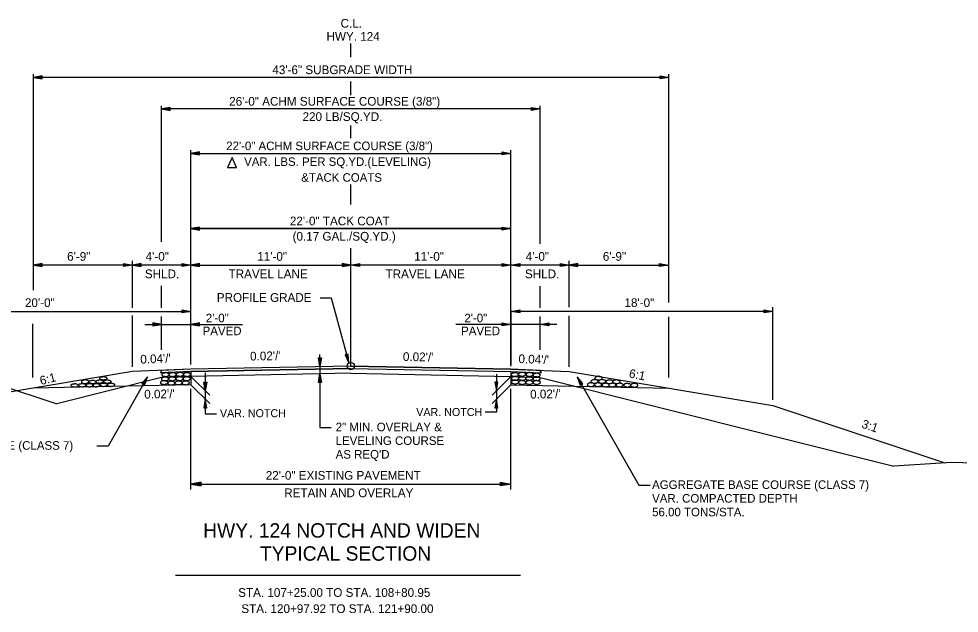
# Model space of a CAD drawing. Extents: x 1824008 to 1828864, y 689441 to 689870.
# Drawn here: x 1828762.4 to 1828827, y 689829.6 to 689870.4 of the extents above; entities that cross this region are included whole.
import ezdxf

# ---------------------------------------------------------------- set-up
doc = ezdxf.new("R2010")
doc.units = 0
for name, color, linetype in [('1', 7, 'Continuous'), ('10', 7, 'Continuous'), ('19', 7, 'Continuous'), ('Level 1', 7, 'Continuous'), ('R_Draft', 7, 'Continuous'), ('R_Horz Alg', 7, 'Continuous')]:
    doc.layers.add(name, color=color, linetype=linetype)

# ---------------------------------------------------------------- blocks, each defined once
blk = doc.blocks.new('ROCKS')
at = {"layer": '1'}
blk.add_spline([(0.013, 0.06), (0.053, 0.053), (0.107, 0.033), (0.133, 0.013), (0.133, -0.007), (0.12, -0.033), (0.107, -0.04), (0.073, -0.053), (0.033, -0.067), (0.013, -0.067), (-0.02, -0.06), (-0.06, -0.053), (-0.087, -0.047), (-0.113, -0.02), (-0.113, -0.007), (-0.107, 0.02), (-0.087, 0.033), (-0.067, 0.047), (-0.033, 0.053), (-0.02, 0.06), (0.013, 0.06)], degree=3, dxfattribs=at)
blk = doc.blocks.new('4TO1 ABC')
at = {"layer": '1', "xscale": 0.1312491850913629, "yscale": 0.1312491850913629, "rotation": 180}
for p in [(0.00175, -0.00875), (-0.03325, -0.0385), (-0.016625, -0.023625), (0, -0.0385), (0.018375, -0.023625), (0.034125, -0.04025), (0.051625, -0.025375), (0.06475, -0.04025), (0.098, -0.04025), (0.133, -0.041125)]:
    blk.add_blockref('ROCKS', p, dxfattribs=at)

msp = doc.modelspace()

# ---------------------------------------------------------------- linework, layer by layer
at = {"layer": '1'}
for p, q in [((1828764.008, 689866.485), (1828763.408, 689866.38)), ((1828763.408, 689866.38), (1828764.008, 689866.275)), ((1828764.008, 689866.43), (1828763.568, 689866.395)), ((1828763.568, 689866.365), (1828764.008, 689866.325)), ((1828764.008, 689866.275), (1828764.008, 689866.485)), ((1828806.466, 689866.275), (1828806.466, 689866.485)), ((1828806.466, 689866.485), (1828807.066, 689866.38)), ((1828806.466, 689866.43), (1828806.906, 689866.395)), ((1828807.066, 689866.38), (1828806.466, 689866.275)), ((1828806.906, 689866.365), (1828806.466, 689866.325)), ((1828772.815, 689864.317), (1828772.215, 689864.212)), ((1828772.215, 689864.212), (1828772.815, 689864.107)), ((1828772.815, 689864.262), (1828772.375, 689864.227)), ((1828772.375, 689864.197), (1828772.815, 689864.157)), ((1828772.815, 689864.107), (1828772.815, 689864.317)), ((1828797.624, 689864.107), (1828797.624, 689864.317)), ((1828797.624, 689864.317), (1828798.224, 689864.212)), ((1828797.624, 689864.262), (1828798.064, 689864.227)), ((1828798.224, 689864.212), (1828797.624, 689864.107)), ((1828798.064, 689864.197), (1828797.624, 689864.157)), ((1828774.82, 689861.268), (1828774.22, 689861.163)), ((1828774.22, 689861.163), (1828774.82, 689861.058)), ((1828774.82, 689861.213), (1828774.38, 689861.178)), ((1828774.82, 689861.058), (1828774.82, 689861.268)), ((1828795.62, 689861.058), (1828795.62, 689861.268)), ((1828795.62, 689861.268), (1828796.22, 689861.163)), ((1828795.62, 689861.213), (1828796.06, 689861.178)), ((1828796.22, 689861.163), (1828795.62, 689861.058)), ((1828774.38, 689861.148), (1828774.82, 689861.108)), ((1828777.071, 689860.871), (1828776.754, 689860.203)), ((1828777.363, 689860.203), (1828777.071, 689860.871)), ((1828796.06, 689861.148), (1828795.62, 689861.108)), ((1828776.754, 689860.203), (1828777.363, 689860.203)), ((1828774.82, 689856.097), (1828774.22, 689855.992)), ((1828774.22, 689855.992), (1828774.82, 689855.887)), ((1828774.82, 689856.042), (1828774.38, 689856.007)), ((1828774.82, 689855.887), (1828774.82, 689856.097)), ((1828795.62, 689855.887), (1828795.62, 689856.097)), ((1828795.62, 689856.097), (1828796.22, 689855.992)), ((1828795.62, 689856.042), (1828796.06, 689856.007)), ((1828796.22, 689855.992), (1828795.62, 689855.887)), ((1828774.38, 689855.977), (1828774.82, 689855.937)), ((1828796.06, 689855.977), (1828795.62, 689855.937)), ((1828764.008, 689853.591), (1828763.408, 689853.486)), ((1828763.408, 689853.486), (1828764.008, 689853.381)), ((1828764.008, 689853.536), (1828763.568, 689853.501)), ((1828763.568, 689853.471), (1828764.008, 689853.431)), ((1828764.008, 689853.381), (1828764.008, 689853.591)), ((1828769.62, 689853.381), (1828769.62, 689853.591)), ((1828769.62, 689853.591), (1828770.22, 689853.486)), ((1828769.62, 689853.536), (1828770.06, 689853.501)), ((1828770.22, 689853.486), (1828769.62, 689853.381)), ((1828770.06, 689853.471), (1828769.62, 689853.431)), ((1828770.22, 689850.55), (1828770.22, 689853.786)), ((1828770.82, 689853.591), (1828770.22, 689853.486)), ((1828770.22, 689853.486), (1828770.82, 689853.381)), ((1828770.82, 689853.536), (1828770.38, 689853.501)), ((1828770.38, 689853.471), (1828770.82, 689853.431)), ((1828770.82, 689853.381), (1828770.82, 689853.591)), ((1828773.62, 689853.381), (1828773.62, 689853.591)), ((1828773.62, 689853.591), (1828774.22, 689853.486)), ((1828773.62, 689853.536), (1828774.06, 689853.501)), ((1828774.22, 689853.486), (1828773.62, 689853.381)), ((1828774.06, 689853.471), (1828773.62, 689853.431)), ((1828774.22, 689846.656), (1828774.22, 689853.786)), ((1828774.82, 689853.591), (1828774.22, 689853.486)), ((1828774.22, 689853.486), (1828785.22, 689853.486)), ((1828774.22, 689853.486), (1828774.82, 689853.381)), ((1828774.82, 689853.536), (1828774.38, 689853.501)), ((1828774.38, 689853.471), (1828774.82, 689853.431)), ((1828774.82, 689853.381), (1828774.82, 689853.591)), ((1828775.22, 689853.486), (1828785.22, 689853.486)), ((1828775.22, 689853.486), (1828785.22, 689853.486)), ((1828784.62, 689853.591), (1828784.62, 689853.381)), ((1828785.22, 689853.486), (1828784.62, 689853.591)), ((1828784.62, 689853.591), (1828784.62, 689853.381)), ((1828785.22, 689853.486), (1828784.62, 689853.591)), ((1828785.06, 689853.501), (1828784.62, 689853.536)), ((1828785.06, 689853.501), (1828784.62, 689853.536)), ((1828784.62, 689853.381), (1828785.22, 689853.486)), ((1828784.62, 689853.381), (1828785.22, 689853.486)), ((1828784.62, 689853.431), (1828785.06, 689853.471)), ((1828784.62, 689853.431), (1828785.06, 689853.471)), ((1828785.22, 689853.486), (1828785.82, 689853.591)), ((1828785.22, 689853.486), (1828785.82, 689853.591)), ((1828795.22, 689853.486), (1828785.22, 689853.486)), ((1828785.82, 689853.381), (1828785.22, 689853.486)), ((1828796.22, 689853.486), (1828785.22, 689853.486)), ((1828785.82, 689853.381), (1828785.22, 689853.486)), ((1828785.38, 689853.501), (1828785.82, 689853.536)), ((1828785.38, 689853.501), (1828785.82, 689853.536)), ((1828785.82, 689853.431), (1828785.38, 689853.471)), ((1828785.82, 689853.431), (1828785.38, 689853.471)), ((1828785.82, 689853.591), (1828785.82, 689853.381)), ((1828785.82, 689853.591), (1828785.82, 689853.381)), ((1828795.62, 689853.381), (1828795.62, 689853.591)), ((1828795.62, 689853.591), (1828796.22, 689853.486)), ((1828795.62, 689853.536), (1828796.06, 689853.501)), ((1828796.22, 689853.486), (1828795.62, 689853.381)), ((1828796.06, 689853.471), (1828795.62, 689853.431)), ((1828796.22, 689846.656), (1828796.22, 689853.786)), ((1828796.22, 689853.486), (1828796.82, 689853.591)), ((1828796.82, 689853.381), (1828796.22, 689853.486)), ((1828796.38, 689853.501), (1828796.82, 689853.536)), ((1828796.82, 689853.431), (1828796.38, 689853.471)), ((1828796.82, 689853.591), (1828796.82, 689853.381)), ((1828799.62, 689853.381), (1828799.62, 689853.591)), ((1828799.62, 689853.591), (1828800.22, 689853.486)), ((1828799.62, 689853.536), (1828800.06, 689853.501)), ((1828800.22, 689853.486), (1828799.62, 689853.381)), ((1828800.06, 689853.471), (1828799.62, 689853.431)), ((1828800.82, 689853.591), (1828800.22, 689853.486)), ((1828800.22, 689853.486), (1828800.82, 689853.381)), ((1828800.82, 689853.536), (1828800.38, 689853.501)), ((1828800.38, 689853.471), (1828800.82, 689853.431)), ((1828800.82, 689853.381), (1828800.82, 689853.591)), ((1828806.431, 689853.381), (1828806.431, 689853.591)), ((1828806.431, 689853.591), (1828807.031, 689853.486)), ((1828806.431, 689853.536), (1828806.871, 689853.501)), ((1828807.031, 689853.486), (1828806.431, 689853.381)), ((1828806.871, 689853.471), (1828806.431, 689853.431)), ((1828772.22, 689850.55), (1828772.22, 689852.059)), ((1828798.22, 689850.55), (1828798.22, 689852.047)), ((1828754.22, 689850.307), (1828774.22, 689850.307)), ((1828773.62, 689850.202), (1828773.62, 689850.412)), ((1828773.62, 689850.412), (1828774.22, 689850.307)), ((1828773.62, 689850.357), (1828774.06, 689850.322)), ((1828774.22, 689850.307), (1828773.62, 689850.202)), ((1828774.06, 689850.292), (1828773.62, 689850.252)), ((1828796.22, 689850.307), (1828796.82, 689850.412)), ((1828814.22, 689850.307), (1828796.22, 689850.307)), ((1828796.82, 689850.202), (1828796.22, 689850.307)), ((1828796.38, 689850.322), (1828796.82, 689850.357)), ((1828796.82, 689850.252), (1828796.38, 689850.292)), ((1828796.82, 689850.412), (1828796.82, 689850.202)), ((1828813.62, 689850.202), (1828813.62, 689850.412)), ((1828813.62, 689850.412), (1828814.22, 689850.307)), ((1828813.62, 689850.357), (1828814.06, 689850.322)), ((1828814.22, 689850.307), (1828813.62, 689850.202)), ((1828814.06, 689850.292), (1828813.62, 689850.252)), ((1828770.22, 689846.496), (1828770.22, 689850.032)), ((1828772.22, 689847.657), (1828772.22, 689849.961)), ((1828798.22, 689847.657), (1828798.22, 689849.961)), ((1828751.824, 689848.348), (1828765.008, 689843.953)), ((1828774.22, 689846.336), (1828770.22, 689846.176)), ((1828774.22, 689846.336), (1828770.22, 689846.176)), ((1828785.22, 689846.556), (1828774.22, 689846.336)), ((1828785.22, 689846.556), (1828774.22, 689846.336)), ((1828785.223, 689846.389), (1828774.223, 689846.169)), ((1828785.216, 689846.389), (1828796.22, 689846.169)), ((1828785.22, 689846.556), (1828796.22, 689846.336)), ((1828796.22, 689846.336), (1828800.22, 689846.176)), ((1828772.22, 689845.756), (1828765.008, 689843.953)), ((1828774.226, 689846.169), (1828772.135, 689846.086)), ((1828774.22, 689845.836), (1828772.22, 689845.756)), ((1828774.22, 689846.169), (1828774.22, 689845.253)), ((1828785.22, 689846.056), (1828774.22, 689845.836)), ((1828774.22, 689845.836), (1828775.52, 689844.564)), ((1828785.22, 689846.056), (1828796.22, 689845.836)), ((1828796.22, 689845.836), (1828794.92, 689844.564)), ((1828796.22, 689846.169), (1828796.22, 689845.253)), ((1828796.22, 689846.169), (1828798.305, 689846.086)), ((1828796.22, 689845.836), (1828798.22, 689845.756)), ((1828798.22, 689845.756), (1828822.529, 689839.679)), ((1828774.22, 689845.253), (1828763.379, 689845.036)), ((1828774.22, 689845.253), (1828775.52, 689843.98)), ((1828775.115, 689845.457), (1828775.325, 689845.457)), ((1828775.22, 689844.857), (1828775.115, 689845.457)), ((1828775.205, 689845.017), (1828775.165, 689845.457)), ((1828775.325, 689845.457), (1828775.22, 689844.857)), ((1828775.27, 689845.457), (1828775.235, 689845.017)), ((1828796.22, 689845.253), (1828794.92, 689843.98)), ((1828795.325, 689845.457), (1828795.115, 689845.457)), ((1828795.115, 689845.457), (1828795.22, 689844.857)), ((1828795.17, 689845.457), (1828795.205, 689845.017)), ((1828795.22, 689844.857), (1828795.325, 689845.457)), ((1828795.235, 689845.017), (1828795.275, 689845.457)), ((1828796.22, 689845.253), (1828807.061, 689845.036)), ((1828774.22, 689838.07), (1828774.22, 689844.993)), ((1828796.22, 689838.07), (1828796.22, 689844.993)), ((1828775.22, 689844.274), (1828775.115, 689843.674)), ((1828775.205, 689844.114), (1828775.165, 689843.674)), ((1828775.325, 689843.674), (1828775.22, 689844.274)), ((1828775.27, 689843.674), (1828775.235, 689844.114)), ((1828795.22, 689844.274), (1828795.115, 689843.674)), ((1828795.205, 689844.114), (1828795.165, 689843.674)), ((1828795.325, 689843.674), (1828795.22, 689844.274)), ((1828795.27, 689843.674), (1828795.235, 689844.114)), ((1828814.22, 689843.843), (1828826.024, 689839.908)), ((1828775.115, 689843.674), (1828775.325, 689843.674)), ((1828795.115, 689843.674), (1828795.325, 689843.674)), ((1828774.935, 689838.57), (1828774.22, 689838.445)), ((1828774.935, 689838.319), (1828774.935, 689838.57)), ((1828795.504, 689838.319), (1828795.504, 689838.57)), ((1828795.504, 689838.57), (1828796.22, 689838.445)), ((1828774.22, 689838.445), (1828796.22, 689838.445)), ((1828774.22, 689838.445), (1828774.935, 689838.319)), ((1828774.935, 689838.504), (1828774.41, 689838.462)), ((1828774.41, 689838.427), (1828774.935, 689838.379)), ((1828795.504, 689838.504), (1828796.029, 689838.462)), ((1828796.22, 689838.445), (1828795.504, 689838.319)), ((1828796.029, 689838.427), (1828795.504, 689838.379)), ((1828773.166, 689832.197), (1828796.878, 689832.197))]:
    msp.add_line(p, q, dxfattribs=at)
for points in [[(1828775.22, 689846.079), (1828775.22, 689843.261), (1828775.996, 689843.261)], [(1828795.22, 689846.007), (1828795.22, 689843.396), (1828794.443, 689843.396)], [(1828852.627, 689840.421), (1828844.044, 689840.132), (1828832.759, 689839.746), (1828826.49, 689839.939), (1828822.529, 689839.679)]]:
    msp.add_lwpolyline(points, dxfattribs=at)
msp.add_circle((1828785.215, 689846.554), 0.25, dxfattribs=at)
at = {"layer": '19'}
for p, q in [((1828763.408, 689851.76), (1828763.408, 689866.605)), ((1828807.066, 689866.38), (1828763.408, 689866.38)), ((1828807.066, 689850.917), (1828807.066, 689866.605)), ((1828772.215, 689855.084), (1828772.215, 689864.437)), ((1828798.224, 689854.955), (1828798.224, 689864.437)), ((1828798.224, 689864.212), (1828772.215, 689864.212)), ((1828774.22, 689861.163), (1828796.22, 689861.163)), ((1828774.22, 689854.515), (1828774.22, 689856.217)), ((1828774.22, 689855.992), (1828796.22, 689855.992)), ((1828796.22, 689855.992), (1828774.22, 689855.992)), ((1828796.22, 689856.195), (1828796.22, 689856.217)), ((1828771.06, 689849.418), (1828777.786, 689849.418)), ((1828771.615, 689849.523), (1828771.615, 689849.313)), ((1828772.215, 689849.418), (1828771.615, 689849.523)), ((1828772.055, 689849.433), (1828771.615, 689849.468)), ((1828771.615, 689849.313), (1828772.215, 689849.418)), ((1828771.615, 689849.363), (1828772.055, 689849.403)), ((1828774.815, 689849.523), (1828774.215, 689849.418)), ((1828774.215, 689849.418), (1828774.815, 689849.313)), ((1828774.815, 689849.468), (1828774.375, 689849.433)), ((1828774.375, 689849.403), (1828774.815, 689849.363)), ((1828774.815, 689849.313), (1828774.815, 689849.523)), ((1828799.38, 689849.418), (1828792.437, 689849.418)), ((1828795.624, 689849.313), (1828795.624, 689849.523)), ((1828795.624, 689849.523), (1828796.224, 689849.418)), ((1828795.624, 689849.468), (1828796.064, 689849.433)), ((1828796.224, 689849.418), (1828795.624, 689849.313)), ((1828796.064, 689849.403), (1828795.624, 689849.363)), ((1828798.224, 689849.418), (1828798.824, 689849.523)), ((1828798.824, 689849.313), (1828798.224, 689849.418)), ((1828798.384, 689849.433), (1828798.824, 689849.468)), ((1828798.824, 689849.363), (1828798.384, 689849.403)), ((1828798.824, 689849.523), (1828798.824, 689849.313)), ((1828782.995, 689847.114), (1828783.205, 689847.114)), ((1828783.1, 689846.514), (1828782.995, 689847.114)), ((1828783.085, 689846.674), (1828783.045, 689847.114)), ((1828783.1, 689846.514), (1828783.1, 689847.346)), ((1828783.205, 689847.114), (1828783.1, 689846.514)), ((1828783.15, 689847.114), (1828783.115, 689846.674)), ((1828774.22, 689846.336), (1828772.22, 689846.256)), ((1828785.22, 689846.556), (1828774.22, 689846.336)), ((1828774.223, 689846.169), (1828785.223, 689846.389)), ((1828783.1, 689846.551), (1828783.1, 689842.332)), ((1828796.22, 689846.336), (1828785.22, 689846.556)), ((1828785.223, 689846.389), (1828796.22, 689846.169)), ((1828798.22, 689846.256), (1828796.22, 689846.336)), ((1828770.22, 689846.176), (1828754.22, 689843.509)), ((1828771.251, 689845.815), (1828768.542, 689841.062)), ((1828771.251, 689845.815), (1828770.863, 689845.346)), ((1828771.159, 689845.684), (1828770.907, 689845.321)), ((1828770.998, 689845.269), (1828771.185, 689845.669)), ((1828771.046, 689845.242), (1828771.251, 689845.815)), ((1828772.22, 689846.256), (1828772.135, 689846.086)), ((1828772.22, 689846.256), (1828772.135, 689846.086)), ((1828772.135, 689846.086), (1828774.223, 689846.169)), ((1828782.995, 689845.414), (1828783.1, 689846.014)), ((1828783.05, 689845.414), (1828783.085, 689845.854)), ((1828783.1, 689846.014), (1828783.205, 689845.414)), ((1828783.115, 689845.854), (1828783.155, 689845.414)), ((1828796.22, 689846.169), (1828798.305, 689846.086)), ((1828798.22, 689846.256), (1828798.304, 689846.086)), ((1828798.22, 689846.256), (1828798.304, 689846.086)), ((1828798.305, 689846.086), (1828798.22, 689846.256)), ((1828800.22, 689846.176), (1828814.22, 689843.843)), ((1828800.775, 689845.815), (1828805.019, 689838.371)), ((1828801.163, 689845.346), (1828800.775, 689845.815)), ((1828800.775, 689845.815), (1828800.981, 689845.242)), ((1828800.841, 689845.669), (1828801.024, 689845.267)), ((1828801.115, 689845.319), (1828800.867, 689845.684)), ((1828770.863, 689845.346), (1828771.046, 689845.242)), ((1828783.205, 689845.414), (1828782.995, 689845.414)), ((1828800.981, 689845.242), (1828801.163, 689845.346)), ((1828783.1, 689842.332), (1828783.866, 689842.332)), ((1828768.542, 689841.062), (1828767.775, 689841.062)), ((1828805.019, 689838.371), (1828805.785, 689838.371))]:
    msp.add_line(p, q, dxfattribs=at)
for points in [[(1828774.22, 689853.486), (1828774.22, 689861.384)], [(1828796.22, 689853.486), (1828796.22, 689857.675), (1828796.22, 689861.384)], [(1828774.22, 689853.786), (1828774.22, 689853.786), (1828774.22, 689856.385)]]:
    msp.add_lwpolyline(points, dxfattribs=at)
at = {"layer": 'R_Draft'}
for p, q in [((1828785.22, 689867.761), (1828785.22, 689868.704)), ((1828785.22, 689865.162), (1828785.22, 689866.104)), ((1828785.22, 689862.201), (1828785.22, 689863.08)), ((1828785.22, 689857.657), (1828785.22, 689859.014)), ((1828785.22, 689846.556), (1828785.22, 689854.643)), ((1828770.22, 689853.486), (1828763.408, 689853.486)), ((1828774.22, 689853.486), (1828770.22, 689853.486)), ((1828775.22, 689853.486), (1828785.22, 689853.486)), ((1828784.62, 689853.591), (1828784.62, 689853.381)), ((1828785.22, 689853.486), (1828784.62, 689853.591)), ((1828785.06, 689853.501), (1828784.62, 689853.536)), ((1828784.62, 689853.381), (1828785.22, 689853.486)), ((1828784.62, 689853.431), (1828785.06, 689853.471)), ((1828785.22, 689853.486), (1828785.82, 689853.591)), ((1828795.22, 689853.486), (1828785.22, 689853.486)), ((1828785.82, 689853.381), (1828785.22, 689853.486)), ((1828785.38, 689853.501), (1828785.82, 689853.536)), ((1828785.82, 689853.431), (1828785.38, 689853.471)), ((1828785.82, 689853.591), (1828785.82, 689853.381)), ((1828800.22, 689853.486), (1828796.22, 689853.486)), ((1828800.22, 689850.607), (1828800.22, 689853.786)), ((1828800.22, 689853.486), (1828807.031, 689853.486)), ((1828800.22, 689846.496), (1828800.22, 689850.007)), ((1828785.03, 689847.376), (1828784.829, 689847.319)), ((1828784.829, 689847.319), (1828785.088, 689846.769)), ((1828784.874, 689847.329), (1828785.031, 689846.92)), ((1828785.056, 689846.925), (1828784.98, 689847.357)), ((1828785.088, 689846.769), (1828785.03, 689847.376))]:
    msp.add_line(p, q, dxfattribs=at)
msp.add_lwpolyline([(1828783.12, 689851.249), (1828783.857, 689851.248), (1828785.088, 689846.769)], dxfattribs=at)
at = {"layer": 'R_Horz Alg'}
for p, q in [((1828796.22, 689846.556), (1828796.22, 689850.912)), ((1828796.22, 689850.307), (1828796.22, 689846.62)), ((1828814.22, 689844.23), (1828814.22, 689850.607)), ((1828807.061, 689845.756), (1828807.061, 689849.941)), ((1828763.379, 689845.756), (1828763.379, 689849.455))]:
    msp.add_line(p, q, dxfattribs=at)

# ---------------------------------------------------------------- block references
at = {"layer": '19', "xscale": 14.999970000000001, "yscale": -14.999970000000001, "rotation": 180}
msp.add_blockref('4TO1 ABC', (1828768.225, 689845.834), dxfattribs=at)
at = {"layer": '19', "xscale": 14.999970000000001, "yscale": 14.999970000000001}
msp.add_blockref('4TO1 ABC', (1828802.231, 689845.847), dxfattribs=at)
at = {"layer": 'Level 1', "xscale": 2.0116542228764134}
for p, yscale, rotation in [((1828772.431, 689845.673), 2.0116542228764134, 0.3302009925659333), ((1828772.46, 689845.97), 2.0116542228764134, 0.3302009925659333), ((1828772.927, 689845.683), 2.0116542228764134, 0.3302009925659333), ((1828772.956, 689845.973), 2.0116542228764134, 0.3302009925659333), ((1828773.427, 689845.693), 2.0116542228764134, 0.3302009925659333), ((1828773.452, 689845.988), 2.0116542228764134, 0.3302009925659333), ((1828773.924, 689845.691), 2.0116542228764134, 0.3302009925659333), ((1828773.945, 689845.978), 2.0116542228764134, 0.3302009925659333), ((1828796.469, 689845.974), 2.0116542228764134, 0.3302009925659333), ((1828796.484, 689845.717), 2.0116542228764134, 0.3302009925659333), ((1828796.965, 689845.997), 2.0116542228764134, 0.3302009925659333), ((1828796.977, 689845.71), 2.0116542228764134, 0.3302009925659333), ((1828797.473, 689845.713), 2.0116542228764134, 0.3302009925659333), ((1828797.486, 689845.983), 2.0116542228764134, 0.3302009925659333), ((1828797.968, 689845.94), 2.0116542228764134, 0.3302009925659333), ((1828797.969, 689845.685), 2.0116542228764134, 0.3302009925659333), ((1828766.94, 689845.48), 2.011654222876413, 1.8621306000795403), ((1828772.368, 689845.428), 2.0116542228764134, 0.3302009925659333), ((1828772.863, 689845.388), 2.0116542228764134, 0.3302009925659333), ((1828773.363, 689845.404), 2.0116542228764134, 0.3302009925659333), ((1828773.86, 689845.404), 2.0116542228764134, 0.3302009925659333), ((1828796.485, 689845.463), 2.0116542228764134, 0.3302009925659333), ((1828796.971, 689845.431), 2.0116542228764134, 0.3302009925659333), ((1828797.472, 689845.431), 2.0116542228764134, 0.3302009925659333), ((1828797.971, 689845.431), 2.0116542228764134, 0.3302009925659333), ((1828803.457, 689845.48), 2.0116542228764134, 0.3302009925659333), ((1828804.672, 689845.237), 2.0116542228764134, 0.3302009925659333)]:
    msp.add_blockref('ROCKS', p, dxfattribs=dict(at, yscale=yscale, rotation=rotation))

# ---------------------------------------------------------------- texts
at = {"layer": '1'}
for s, height, p in [('C.L.', 0.6, (1828784.514, 689869.796)), ('HWY. 124', 0.6, (1828783.55, 689868.896)), ('43\'-6" SUBGRADE WIDTH', 0.6, (1828779.828, 689866.605)), ('26\'-0" ACHM SURFACE COURSE (3/8")', 0.6, (1828776.862, 689864.437)), ('220 LB/SQ.YD.', 0.6, (1828781.903, 689863.387)), ('22\'-0" TACK COAT', 0.6, (1828781.031, 689856.217)), ('(0.17 GAL./SQ.YD.)', 0.6, (1828781.218, 689855.167)), ('SHLD.', 0.6, (1828771.067, 689852.586)), ('2\'-0"', 0.59, (1828793.021, 689849.559)), ('PAVED', 0.59, (1828792.798, 689848.674)), ('22\'-0" EXISTING PAVEMENT', 0.6, (1828779.376, 689838.745)), ('RETAIN AND OVERLAY', 0.6, (1828780.644, 689837.545))]:
    msp.add_text(s, height=height, dxfattribs=at).set_placement(p)
for s, height, rotation, p in [('22\'-0" ACHM SURFACE COURSE (3/8")', 0.58757, 360, (1828776.659, 689861.383)), ('VAR. LBS. PER SQ.YD.(LEVELING)', 0.58757, 360, (1828777.889, 689860.297)), ('&TACK COATS', 0.58757, 360, (1828781.813, 689859.212)), ('2\'-0"', 0.59, 360, (1828775.258, 689849.559)), ('PAVED', 0.59, 360, (1828775.035, 689848.674)), ("0.02'/'", 0.6, 1.14576, (1828778.302, 689846.928)), ("0.04'/'", 0.6, 2.29061, (1828770.764, 689846.713)), ("0.02'/'", 0.6, 358.85424, (1828788.793, 689846.907)), ('6:1', 0.6, 348.57628, (1828804.293, 689845.779)), ('6:1', 0.6, 14.03624, (1828763.929, 689845.244)), ("0.02'/'", 0.6, 1.14576, (1828771.03, 689844.315)), ("0.02'/'", 0.6, 1.14576, (1828797.543, 689844.315)), ('2" MIN. OVERLAY &', 0.59001, 360, (1828784.175, 689842.074)), ('3:1', 0.6, 341.56505, (1828820.271, 689842.332)), ('LEVELING COURSE', 0.59001, 360, (1828784.175, 689841.134)), ("AS REQ'D", 0.59, 360, (1828784.175, 689840.194)), (' HWY. 124 NOTCH AND WIDEN', 0.98999, 359.99538, (1828774.704, 689834.769)), ('TYPICAL SECTION ', 0.98999, 359.99538, (1828778.972, 689833.185))]:
    msp.add_text(s, height=height, rotation=rotation, dxfattribs=at).set_placement(p)
at = {"layer": '10'}
for p in [(1828776.224, 689843.041), (1828789.714, 689843.121)]:
    msp.add_text('VAR. NOTCH', height=0.55, dxfattribs=at).set_placement(p)
at = {"layer": '19'}
for s, p in [('AGGREGATE BASE COURSE (CLASS 7)', (1828751.238, 689840.804)), ('AGGREGATE BASE COURSE (CLASS 7)', (1828805.919, 689838.112)), ('VAR. COMPACTED DEPTH', (1828805.919, 689837.172)), ('56.00 TONS/STA.', (1828805.919, 689836.232))]:
    msp.add_text(s, height=0.59001, rotation=360, dxfattribs=at).set_placement(p)
at = {"layer": 'R_Draft'}
for s, p in [('6\'-9"', (1828765.725, 689853.786)), ('4\'-0"', (1828771.121, 689853.786)), ('11\'-0"', (1828778.791, 689853.786)), ('11\'-0"', (1828789.574, 689853.786)), ('4\'-0"', (1828797.238, 689853.786)), ('6\'-9"', (1828802.536, 689853.786)), ('TRAVEL LANE', (1828776.819, 689852.586)), ('TRAVEL LANE', (1828787.601, 689852.586)), ('SHLD.', (1828797.184, 689852.586)), ('PROFILE GRADE', (1828776.011, 689850.963)), ('20\'-0"', (1828762.828, 689850.607)), ('18\'-0"', (1828804.022, 689850.607))]:
    msp.add_text(s, height=0.6, dxfattribs=at).set_placement(p)
for s, rotation, p in [("0.04'/'", 357.70939, (1828796.728, 689846.765)), ('STA. 107+25.00 TO STA. 108+80.95', 359.99538, (1828777.48, 689830.698)), ('STA. 120+97.92 TO STA. 121+90.00', 359.99538, (1828777.695, 689829.588))]:
    msp.add_text(s, height=0.6, rotation=rotation, dxfattribs=at).set_placement(p)

doc.saveas('drawing.dxf')
